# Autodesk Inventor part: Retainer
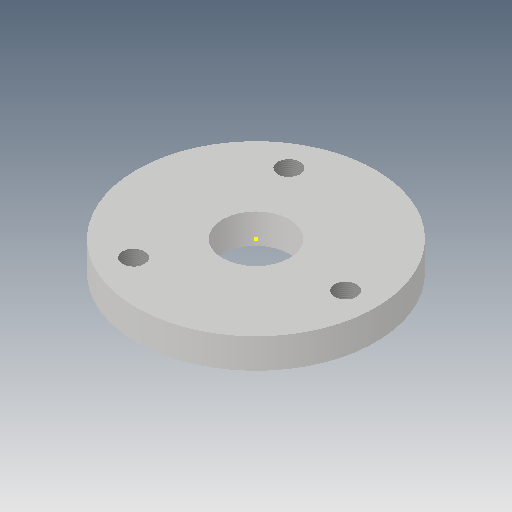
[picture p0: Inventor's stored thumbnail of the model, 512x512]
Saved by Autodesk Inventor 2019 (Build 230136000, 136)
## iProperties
Created: 2016-05
Part Number: Retainer
Material: Generic
Document SubType Name: Modeling
Designer: CADCIM
Density: 1 g/cm^3
Appearance: Default
Author: CADCIM
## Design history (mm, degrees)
sketch "Sketch1"
  geometry: C1 r 100 at (0, 0); 1 further point
  constraints: 1 centre point, 1 coincident
  dimensions: "d0" = 200 diameter of C1
extrude "Extrusion1" new body sketch "Sketch1" distance "d1" = 25; taper "d2" = 0 deg
sketch "Sketch2"
  geometry: 1 further point
sketch "Sketch3" dims "d3" = 150
  geometry: L1 (0, 0)-(102.916, 0); 2 further points
  constraints: 2 end point, 1 coincident, 1 horizontal, 1 horizontal alignment, 1 point on line, 2 other
hole "Hole1" sketch "Sketch3" at (75, 0) diameter "d4" = 18.376; stored, may be unused: countersink angle "d8" = 90 deg, drill point angle "d10" = 118 deg; dims "d5" = 40, "d6" = 4, "d7" = 2, "d9" = 47.3
pattern_circular "Circular Pattern1" dims angle "d12" = 360 deg
sketch "Sketch4"
  geometry: C1 r 28 at (0, 0); 1 further point
  constraints: 1 centre point, 1 coincident
  dimensions: "d14" = 56 diameter of C1
extrude "Extrusion2" cut sketch "Sketch4" distance "d15" = 25; taper "d16" = 0 deg
body "Solid1"
